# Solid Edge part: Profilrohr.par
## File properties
Username: bmolnar
Dokumentum tartalom típus: 0
Author: bmolnar
Last saved by: bmolnar
Revision: 78
Sűrűség: 0,000 kg/m^3
Pontosság: 0,990
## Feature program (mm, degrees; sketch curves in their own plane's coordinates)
base feature "unnamed BaseFeature 1"
thread "unnamed Thread 1"
thread "Menet_2"  ThreadDepth = 5.5 mm
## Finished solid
Body 1: solid body, 127 faces, 307 edges, 198 vertices.
  Faces by surface: cylinder 57, plane 52, cone 16, torus 2
  Edges by curve: line 144, circle 142, spline 9, curve on surface 7, intersection 5
Bounding box of the edges (mm; curved faces can reach further): 30.000 x 34.000 x 42.000, from (-15, -15, 0) to (15, 19, 42).
Cylindrical faces by radius (mm): R0.3 x24, R0.65 x2, R1.85 x4, R2 x2, R2.067 x4, R2.35 x2, R2.8 x4, R3.75 x4, R8 x1, R8.95 x2, R9.1 x2, R9.5 x2, R20 x4
Conical faces (half-angle, radius in mm at the cone's reference point): 45 deg R2.317 x2, 45 deg R2.95 x4, 45 deg R3.9 x4, 45 deg R8.4 x2, 45 deg R9.2 x2, 45 deg R9.25 x2
Toroidal faces (ring radius, tube radius in mm): R9.4 r0.1 x2
Planar faces by outward normal: +x 6, +y 9, +z 9, -x 6, -y 5, -z 9, oblique 8
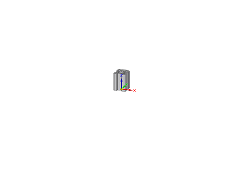
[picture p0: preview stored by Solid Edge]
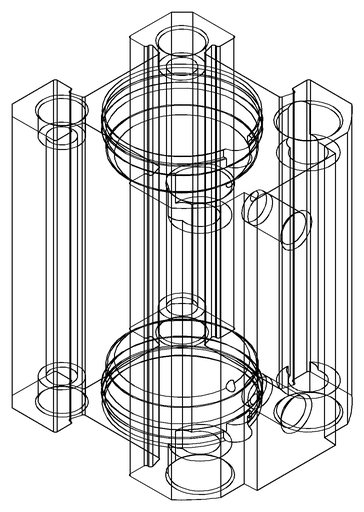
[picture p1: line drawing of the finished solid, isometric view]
